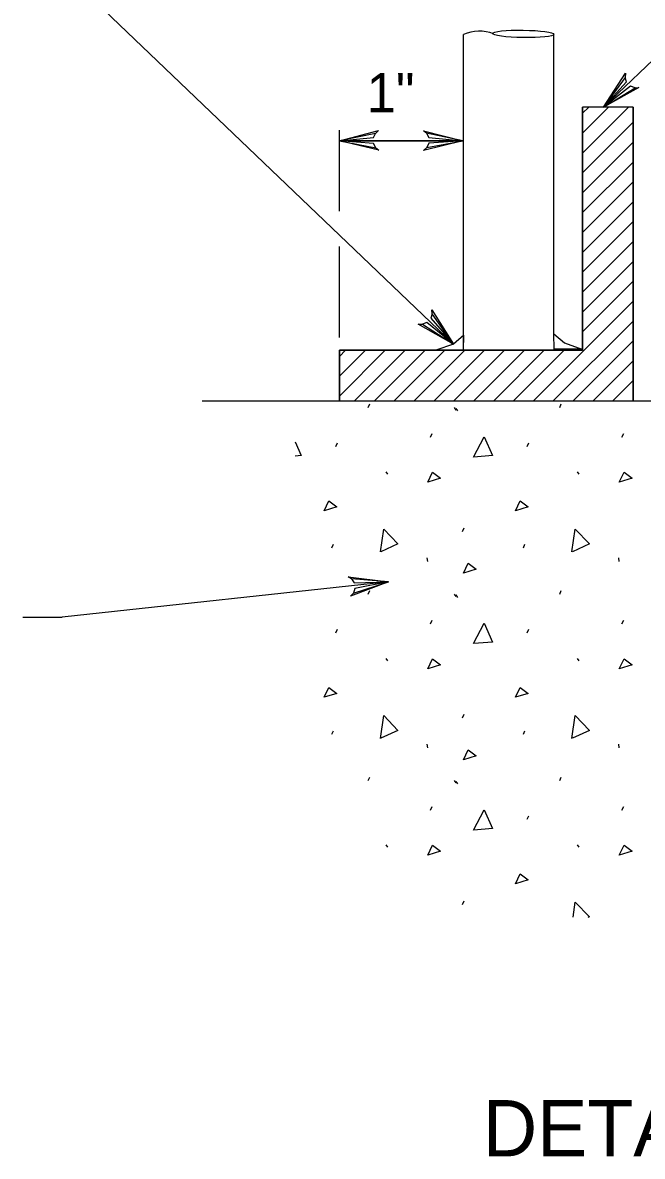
# Model space of a CAD drawing. Extents: x 636462 to 639890, y 299944 to 300538.
# Drawn here: x 639431.6 to 639486.6, y 300363.2 to 300464 of the extents above; entities that cross this region are included whole.
import ezdxf

# ---------------------------------------------------------------- set-up
doc = ezdxf.new("R2010")
doc.units = 0
doc.layers.add('Default', color=7, linetype='Continuous')

msp = doc.modelspace()

# ---------------------------------------------------------------- linework, layer by layer
at = {"layer": 'Default'}
for p, q in [((639483.19, 300456.49), (639505.64, 300478)), ((639469.85, 300435.43), (639438.82, 300465.12)), ((639470.75, 300434.89), (639470.75, 300462.96)), ((639478.78, 300435.78), (639478.78, 300462.96)), ((639481.33, 300434.89), (639481.33, 300456.49)), ((639485.83, 300456.49), (639481.33, 300456.49)), ((639481.33, 300455.95), (639481.87, 300456.49)), ((639481.33, 300454.18), (639483.64, 300456.49)), ((639481.33, 300452.42), (639485.41, 300456.49)), ((639485.83, 300456.49), (639485.83, 300430.39)), ((639459.72, 300447.26), (639459.72, 300454.45)), ((639481.33, 300450.65), (639485.83, 300455.15)), ((639470.47, 300453.51), (639459.72, 300453.51)), ((639459.72, 300453.51), (639470.7, 300453.51)), ((639470.7, 300453.51), (639464.39, 300453.51)), ((639481.33, 300448.88), (639485.83, 300453.38)), ((639481.33, 300447.12), (639485.83, 300451.62)), ((639481.33, 300445.35), (639485.83, 300449.85)), ((639481.33, 300443.58), (639485.83, 300448.08)), ((639481.33, 300441.82), (639485.83, 300446.32)), ((639481.33, 300440.05), (639485.83, 300444.55)), ((639459.72, 300436.01), (639459.72, 300444.11)), ((639481.33, 300438.28), (639485.83, 300442.78)), ((639481.33, 300436.52), (639485.83, 300441.02)), ((639476.96, 300430.39), (639485.83, 300439.25)), ((639478.73, 300430.39), (639485.83, 300437.48)), ((639480.5, 300430.39), (639485.83, 300435.72)), ((639459.72, 300434.89), (639481.33, 300434.89)), ((639459.72, 300430.39), (639459.72, 300434.89)), ((639459.72, 300434.34), (639460.27, 300434.89)), ((639459.72, 300432.58), (639462.03, 300434.89)), ((639459.72, 300430.81), (639463.8, 300434.89)), ((639461.07, 300430.39), (639465.57, 300434.89)), ((639462.83, 300430.39), (639467.33, 300434.89)), ((639464.6, 300430.39), (639469.1, 300434.89)), ((639466.37, 300430.39), (639470.87, 300434.89)), ((639468.13, 300430.39), (639472.63, 300434.89)), ((639469.9, 300430.39), (639474.4, 300434.89)), ((639471.66, 300430.39), (639476.17, 300434.89)), ((639473.43, 300430.39), (639477.93, 300434.89)), ((639475.2, 300430.39), (639479.7, 300434.89)), ((639482.26, 300430.39), (639485.83, 300433.95)), ((639484.03, 300430.39), (639485.83, 300432.18)), ((639447.54, 300430.39), (639474.92, 300430.39)), ((639462.29, 300429.79), (639462.43, 300430.11)), ((639474.92, 300430.39), (639513.48, 300430.39)), ((639479.3, 300429.79), (639479.44, 300430.11)), ((639485.8, 300430.39), (639485.83, 300430.42)), ((639469.92, 300429.79), (639470.07, 300429.57)), ((639470.07, 300429.71), (639470.21, 300429.49)), ((639467.83, 300427.16), (639467.97, 300427.48)), ((639484.83, 300427.16), (639484.98, 300427.48)), ((639459.42, 300426.34), (639459.56, 300426.66)), ((639476.42, 300426.34), (639476.56, 300426.66)), ((639463.85, 300424.07), (639464, 300423.86)), ((639480.86, 300424.07), (639481, 300423.86)), ((639470.67, 300418.78), (639470.81, 300419.1)), ((639459.06, 300417.32), (639459.2, 300417.64)), ((639476.07, 300417.32), (639476.21, 300417.64)), ((639467.5, 300416.43), (639467.54, 300416.11)), ((639484.51, 300416.43), (639484.54, 300416.11)), ((639464.09, 300414.29), (639435.09, 300411.14)), ((639462.29, 300413.21), (639462.43, 300413.53)), ((639469.92, 300413.21), (639470.07, 300412.99)), ((639470.07, 300413.13), (639470.21, 300412.91)), ((639479.3, 300413.21), (639479.44, 300413.53)), ((639431.59, 300411.14), (639435.09, 300411.14)), ((639467.83, 300410.57), (639467.97, 300410.89)), ((639484.83, 300410.57), (639484.98, 300410.89)), ((639459.42, 300409.76), (639459.56, 300410.08)), ((639476.42, 300409.76), (639476.56, 300410.08)), ((639463.85, 300407.49), (639464, 300407.27)), ((639480.86, 300407.49), (639481, 300407.27)), ((639470.67, 300402.2), (639470.81, 300402.52)), ((639459.06, 300400.74), (639459.2, 300401.06)), ((639476.07, 300400.74), (639476.21, 300401.06)), ((639467.5, 300399.85), (639467.54, 300399.53)), ((639484.51, 300399.85), (639484.54, 300399.53)), ((639462.29, 300396.62), (639462.43, 300396.94)), ((639479.3, 300396.62), (639479.44, 300396.94)), ((639469.92, 300396.62), (639470.07, 300396.41)), ((639470.07, 300396.54), (639470.21, 300396.33)), ((639467.83, 300393.99), (639467.97, 300394.31)), ((639484.83, 300393.99), (639484.98, 300394.31)), ((639476.42, 300393.18), (639476.56, 300393.5)), ((639463.85, 300390.9), (639464, 300390.69)), ((639480.86, 300390.9), (639481, 300390.69)), ((639470.67, 300385.62), (639470.81, 300385.94))]:
    msp.add_line(p, q, dxfattribs=at)
for points in [[(639485.99, 300458.22), (639486.34, 300458.24), (639483.19, 300456.49), (639485.99, 300458.22), (639485.6, 300458.36), (639483.19, 300456.49), (639485.24, 300458.74), (639485.11, 300459.14), (639483.19, 300456.49), (639485.15, 300459.52), (639485.11, 300459.14)], [(639462.96, 300452.89), (639463.23, 300452.67), (639459.72, 300453.51), (639462.96, 300452.89), (639462.76, 300453.26), (639459.72, 300453.51), (639462.75, 300453.79), (639462.93, 300454.16), (639459.72, 300453.51), (639463.21, 300454.42), (639462.93, 300454.16)], [(639467.47, 300454.17), (639467.21, 300454.4), (639470.7, 300453.51), (639467.47, 300454.17), (639467.67, 300453.8), (639470.7, 300453.51), (639467.67, 300453.28), (639467.48, 300452.9), (639470.7, 300453.51), (639467.2, 300452.65), (639467.48, 300452.9)], [(639467.97, 300438.13), (639467.93, 300438.48), (639469.85, 300435.43), (639467.97, 300438.13), (639467.85, 300437.73), (639469.85, 300435.43), (639467.49, 300437.34), (639467.1, 300437.2), (639469.85, 300435.43), (639466.72, 300437.21), (639467.1, 300437.2)], [(639471.63, 300425.38), (639472.59, 300427.19), (639473.33, 300425.52), (639471.66, 300425.38)], [(639455.79, 300426.74), (639456.33, 300425.52), (639455.79, 300425.48)], [(639467.58, 300423.15), (639468.01, 300424.03), (639468.72, 300423.5), (639467.58, 300423.15)], [(639484.59, 300423.15), (639485.01, 300424.03), (639485.72, 300423.5), (639484.59, 300423.15)], [(639458.36, 300420.61), (639458.78, 300421.5), (639459.49, 300420.96), (639458.36, 300420.61)], [(639475.36, 300420.61), (639475.79, 300421.5), (639476.5, 300420.96), (639475.36, 300420.61)], [(639463.38, 300416.96), (639463.66, 300418.99), (639464.93, 300417.67), (639463.41, 300416.97)], [(639480.38, 300416.96), (639480.67, 300418.99), (639481.94, 300417.67), (639480.42, 300416.97)], [(639470.74, 300415.05), (639471.17, 300415.94), (639471.88, 300415.41), (639470.74, 300415.05)], [(639460.8, 300414.56), (639460.51, 300414.75), (639464.09, 300414.29), (639460.8, 300414.56), (639461.04, 300414.21), (639464.09, 300414.29), (639461.1, 300413.69), (639460.97, 300413.29), (639464.09, 300414.29), (639460.71, 300413.01), (639460.97, 300413.29)], [(639471.63, 300408.8), (639472.59, 300410.61), (639473.33, 300408.94), (639471.66, 300408.8)], [(639467.58, 300406.56), (639468.01, 300407.45), (639468.72, 300406.92), (639467.58, 300406.56)], [(639484.59, 300406.56), (639485.01, 300407.45), (639485.72, 300406.92), (639484.59, 300406.56)], [(639458.36, 300404.03), (639458.78, 300404.91), (639459.49, 300404.38), (639458.36, 300404.03)], [(639475.36, 300404.03), (639475.79, 300404.91), (639476.5, 300404.38), (639475.36, 300404.03)], [(639463.38, 300400.37), (639463.66, 300402.4), (639464.93, 300401.09), (639463.41, 300400.39)], [(639480.38, 300400.37), (639480.67, 300402.4), (639481.94, 300401.09), (639480.42, 300400.39)], [(639470.74, 300398.47), (639471.17, 300399.36), (639471.88, 300398.83), (639470.74, 300398.47)], [(639471.63, 300392.22), (639472.59, 300394.03), (639473.33, 300392.36), (639471.66, 300392.22)], [(639467.58, 300389.98), (639468.01, 300390.87), (639468.72, 300390.34), (639467.58, 300389.98)], [(639484.59, 300389.98), (639485.01, 300390.87), (639485.72, 300390.34), (639484.59, 300389.98)], [(639475.36, 300387.44), (639475.79, 300388.33), (639476.5, 300387.8), (639475.36, 300387.44)], [(639480.48, 300384.47), (639480.67, 300385.82), (639481.94, 300384.51), (639481.8, 300384.44)]]:
    msp.add_lwpolyline(points, dxfattribs=at)
for points in [[(639478.51, 300434.89), (639459.72, 300434.89), (639459.72, 300430.39), (639485.83, 300430.39), (639485.83, 300456.49), (639481.33, 300456.49), (639481.33, 300434.89)], [(639470.78, 300436.23), (639469.85, 300435.43), (639468.3, 300434.89), (639470.75, 300434.89)], [(639478.78, 300436.33), (639479.71, 300435.53), (639481.26, 300434.99), (639478.81, 300434.99)]]:
    msp.add_lwpolyline(points, close=True, dxfattribs=at)
msp.add_arc((639472.15, 300459.7), 3.55, 69.2636, 113.1646, dxfattribs=at)
msp.add_ellipse((639476.05, 300463.01), major_axis=(-2.73, 0.04), ratio=0.121225, start_param=0, end_param=6.283175, dxfattribs=at)

# ---------------------------------------------------------------- texts
for s, height, p in [('1"', 3.498, (639462.14, 300456.03)), ('DETAIL A', 4.997, (639472.47, 300363.22))]:
    msp.add_text(s, height=height, dxfattribs=at).set_placement(p)

doc.saveas('drawing.dxf')
